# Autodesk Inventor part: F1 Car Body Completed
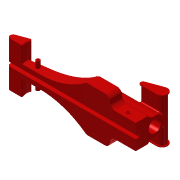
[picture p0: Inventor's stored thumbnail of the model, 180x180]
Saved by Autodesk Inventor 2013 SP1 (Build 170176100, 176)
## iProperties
Created: 2013-01
Part Number: F1 Car Body Completed
Material: Generic
Document SubType Name: Modeling
Designer: banachd
Density: 0.55 g/cm^3
Mass: 113.444 g
Surface Area: 400.752 cm^2
Volume: 206.262 cm^3
Description: CAR BODY
Author: banachd
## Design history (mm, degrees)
sketch "Sketch1"
  geometry: L1 (0, 0)-(200, 0); L2 (200, 0)-(200, 20); L3 (200, 20)-(110, 20); L4 (0, 8)-(0, 0); A1 r 510.167 centre (110, -490.167) between (110, 20) and (0, 8)
  constraints: 8 end point, 2 perpendicular, 2 point on circle, 1 centre point, 1 horizontal, 1 parallel, 1 tangent
  dimensions: "d0" = 200 distance of L1.start L1.end; "d1" = 20 distance of L1.end L2.end; "d2" = 90 distance of L2.end L3.end; "d3" = 8 distance of L4.start L1.start
extrude "Extrusion1" new body sketch "Sketch1" distance "d4" = 35; taper "d5" = 0 deg
sketch "Sketch2"
  geometry: L1 (0, 0)-(200, 0) reference; L2 (0, 35)-(200, 35) reference; L3 (0, 0)-(0, 35) reference; L4 (0, 10)-(50, 10); L5 (200, 35)-(160, 35); L6 (160, 35)-(160, 19); L7 (160, 19)-(200, 19); L8 (200, 19)-(200, 35); A1 r 120 centre (50, 130) between (50, 10) and (123.314, 35)
  constraints: 10 end point, 3 parallel, 2 point on circle, 2 point on line, 1 centre point, 1 horizontal, 1 perpendicular, 1 tangent
  dimensions: "d6" = 50 distance of L4.start L4.end; "d7" = 40 distance of L7.end L6.end; "d8" = 16 distance of L6.end L5.end; "d9" = 10 distance between parallel lines of L4 L1; "d10" = 120 radius of A1
extrude "Extrusion2" cut sketch "Sketch2" stored distance "d11" = 0; taper "d12" = 0 deg
sketch "Sketch3"
  geometry: L1 (0, 0)-(0, 8) reference; L2 (50, 0)-(0, 0) reference; C1 r 3 at (40, 8)
  constraints: 1 centre point
  dimensions: "d13" = 6 diameter of C1; "d15" = 8 distance from line of C1.centre L2; "d17" = 40 distance from line of C1.centre L1
extrude "Extrusion3" join sketch "Sketch3" distance "d18" = 10; taper "d19" = 0 deg
hole "Hole1" diameter "d22" = 3; stored, may be unused: countersink angle "d26" = 90 deg, drill point angle "d28" = 118 deg; dims "d20" = 10, "d21" = 10, "d23" = 6, "d24" = 4, "d25" = 2, "d27" = 8
pattern_linear "Rectangular Pattern1"
fillet "Fillet1" dims "d32" = 8
mirror "Mirror1"
sketch "Sketch4"
  geometry: L1 (38, 20)-(0, 20) reference; L2 (5, 20)-(5, 30); L3 (33, 30)-(33, 20); L4 (-8, 0)-(-16, 0) reference; A1 r 14 centre (19, 30) between (33, 30) and (5, 30); 2 further points
  constraints: 4 end point, 2 perpendicular, 2 point on circle, 2 point on line, 2 tangent, 1 centre point, 1 midpoint, 1 vertical alignment
  dimensions: "d33" = 30 distance from line of A1.centre L4; "d34" = 14 radius of A1
extrude "Extrusion4" join sketch "Sketch4" distance "d35" = 80; taper "d36" = 0 deg
sketch "Sketch5"
  geometry: L1 (0, 0)-(0, 8) reference; L2 (110, 20)-(120, 20) reference; L3 (120, 20)-(120, 44) reference; L4 (120, 44)-(200, 44) reference; L5 (200, 44)-(200, 0) reference; L6 (200, 0)-(0, 0) reference; L7 (0, 8)-(25.066, 17.123); L8 (168.592, 41)-(193.592, 41); L9 (191.4, 53.43)-(167.908, 44.879); C1 r 1.5 at (180, 8) reference; C2 r 1.5 at (40, 8) reference; A1 r 510.167 centre (110, -490.167) between (110, 20) and (0, 8) reference; A2 r 17.5 centre (40, 8) between (25.066, 17.123) and (24.436, 0); A3 r 6.408 centre (193.592, 47.408) between (193.592, 41) and (191.4, 53.43); A4 r 2 centre (168.592, 43) between (167.908, 44.879) and (168.592, 41)
  constraints: 6 end point, 6 point on circle, 5 tangent, 3 centre point, 1 coincident, 1 parallel, 1 point on line
  dimensions: "d37" = 17.5 radius of A2; "d38" = 25 distance of L8.start L8.end; "d39" = 2 radius of A4; "d40" = 20 deg angle of L8 L9; "d41" = 20 deg angle of L6 L7; "d42" = 3 distance between parallel lines of L8 L4
  node "Project Cut Edges1"
extrude "Extrusion5" join sketch "Sketch5" stored distance "d43" = 70; taper "d44" = 0 deg
extrude "Extrusion6" join sketch "Sketch5" stored distance "d45" = 70; taper "d46" = 0 deg
hole "Hole2" diameter "d49" = 19.5; stored, may be unused: countersink angle "d53" = 90 deg, drill point angle "d55" = 118 deg; dims "d47" = 10, "d48" = 10, "d50" = 6, "d51" = 4, "d52" = 2, "d54" = 55
sketch "Sketch7"
  geometry: L1 (0, 8)-(25.066, 17.123) reference; L2 (110, 20)-(120, 20) reference; L3 (120, 20)-(120, 44) reference; L4 (120, 44)-(166.86, 44) reference; L5 (167.908, 44.879)-(191.4, 53.43) reference; L6 (199.019, 44)-(200, 44) reference; L7 (200, 44)-(200, 39.75) reference; L8 (200, 39.75)-(145, 39.75) reference; L9 (145, 39.75)-(139.142, 30) reference; L10 (139.142, 30)-(145, 20.25) reference; L11 (145, 20.25)-(200, 20.25) reference; L12 (200, 20.25)-(200, 0) reference; L13 (200, 0)-(0, 0) reference; L14 (0, 0)-(0, 8) reference; L15 (120, 20)-(133.856, 44); C1 r 1.5 at (180, 8) reference; C2 r 1.5 at (40, 8) reference; A1 r 17.5 centre (40, 8) between (25.066, 17.123) and (23.1, 12.544) reference; A2 r 510.167 centre (110, -490.167) between (110, 20) and (23.1, 12.544) reference; A3 r 2 centre (168.592, 43) between (167.908, 44.879) and (166.86, 44) reference; A4 r 6.408 centre (193.592, 47.408) between (199.019, 44) and (191.4, 53.43) reference
  constraints: 2 end point, 1 point on line
  dimensions: "d61" = 30 deg angle of L15 L3
extrude "Extrusion8" cut sketch "Sketch7" stored distance "d62" = 10; taper "d63" = 0 deg
sketch "Sketch6"
  geometry: L1 (168.592, 41)-(193.592, 41) reference; L2 (191.4, 53.43)-(167.908, 44.879) reference; L3 (167.224, 46.759)-(190.716, 55.309); L4 (193.592, 39)-(168.592, 39); A1 r 6.408 centre (193.592, 47.408) between (193.592, 41) and (191.4, 53.43) reference; A2 r 2 centre (168.592, 43) between (167.908, 44.879) and (168.592, 41) reference; A3 r 8.408 centre (193.592, 47.408) between (193.592, 39) and (190.716, 55.309); A4 r 4 centre (168.592, 43) between (167.224, 46.759) and (168.592, 39); 1 further point
  constraints: 4 end point, 4 point on circle, 2 centre point, 3 other
  dimensions: "d56" = 2 distance between parallel lines of L3 L2
extrude "Extrusion7" join sketch "Sketch6" distance "d57" = 1; taper "d58" = 0 deg
mirror "Mirror2"
fillet "Fillet2"
fillet "Fillet3" dims "d59" = 2
fillet "Fillet4" dims "d60" = 7
sketch "Sketch8"
  geometry: L1 (38, 0)-(0, 0) reference; L2 (16, 0)-(22, 0); L3 (22, 0)-(22, 6); L4 (22, 6)-(16, 6); L5 (16, 6)-(16, 0); 2 further points
  constraints: 8 end point, 2 midpoint, 2 parallel, 1 horizontal, 1 perpendicular
  dimensions: "d64" = 6 distance of L4.end L3.end; "d65" = 6 distance of L3.end L2.end
extrude "Extrusion9" cut sketch "Sketch8" stored distance "d66" = 10; taper "d67" = 0 deg
body "Solid1"
node "Project Cut Edges2"
